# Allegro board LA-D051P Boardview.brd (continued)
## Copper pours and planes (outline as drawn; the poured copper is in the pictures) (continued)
VCCSA_B+ on TOP (solid shape): 147.25,118.74 147.25,117.91 147.19,117.85 145.73,117.85 145.47,118.1 145.47,119.18 145.66,119.37 146.61,119.37
VCCSA_B+ on BOTTOM (solid shape): 150.81,121.15 150.81,118.74 150.74,118.67 148.14,118.67 147.38,117.91 145.47,117.91 145.22,118.16 145.22,119.75 145.79,119.75 145.79,120.01 146.87,120.01 146.87,119.43 147.06,119.24 148.71,119.24 148.9,119.43 148.9,119.94 148.71,120.13 147,120.13 146.87,120.01 145.79,120.01 145.79,120.26 145.22,120.26 145.22,121.28 145.41,121.47 150.49,121.47
VDD_1.35V on BOTTOM (solid shape): 83.11,17.14 83.11,16.44 84,15.55 84.58,15.55 84.64,15.49 84.64,14.72 84.51,14.6 84.26,14.6 84.13,14.72 83.62,14.72 81.91,16.44 80.83,16.44 80.77,16.5 80.77,17.14 80.89,17.26 82.99,17.26
VDD_CHG on BOTTOM (solid shape): 45.4,18.91 45.4,17.71 45.27,17.58 45.27,16.37 45.59,16.06 45.59,14.98 45.52,14.91 45.46,14.91 45.4,14.98 45.4,15.93 44.63,16.69 44.63,18.85 44.76,18.98 45.33,18.98
VDDP_CHG on BOTTOM (solid shape): 46.28,18.91 46.28,17.64 46.16,17.52 45.97,17.52 45.78,17.33 45.78,16.37 46.03,16.12 46.03,14.98 45.97,14.91 45.84,14.91 45.78,14.98 45.78,16.06 45.46,16.37 45.46,17.52 45.65,17.71 45.65,18.91 45.71,18.98 46.22,18.98
VIN_1.8VALW on BOTTOM (solid shape): 87.94,25.9 87.94,24.95 86.92,23.93 86.92,23.68 85.15,21.9 84.83,21.9 84.83,22.47 83.43,22.47 83.43,21.9 83.11,21.9 82.99,22.03 82.99,22.6 85.72,25.33 85.72,25.9 85.97,26.15 87.69,26.15
+FAN_POWER on TOP (solid shape): 8.18,71.94 8.18,71.05 8.06,70.92 5.39,70.92 4.88,70.41 4.88,68.76 4.63,68.51 4.12,68.51 3.87,68.76 3.87,71.49 4.18,71.81 4.82,71.81 5.2,72.19 7.93,72.19
+FAN_POWER on BOTTOM (solid shape): 8.06,72.83 8.06,71.05 7.9,70.89 6.69,70.89 6.53,71.05 6.53,73.08 6.58,73.13 7.75,73.13
+GPU_CORE on TOP (solid shape): outline of 281 points within 60.57,70.91 70.35,79.3
+GPU_CORE on TOP (solid shape): outline of 548 points within 45.59,42.98 64.06,59.11
+GPU_CORE on BOTTOM (solid shape): 69.22,76.89 69.22,76.61 69.09,76.48 68.84,76.48 66.67,78.65 66.67,78.82 66.9,79.04 67.06,79.04
+GPU_CORE on BOTTOM (solid shape): 69.22,74.86 69.22,74.56 69.12,74.45 68.85,74.45 64.74,78.56 64.74,78.82 64.85,78.93 65.15,78.93
+GPU_CORE on BOTTOM (solid shape): 69.21,70.88 69.21,70.62 69.07,70.48 68.82,70.48 60.76,78.54 60.76,78.79 60.91,78.94 61.14,78.94
+GPU_CORE on BOTTOM (solid shape): 69.22,72.87 69.22,72.56 69.12,72.46 68.85,72.46 62.8,78.51 62.8,78.8 62.93,78.93 63.16,78.93
+GPU_CORE on BOTTOM (solid shape): 65.26,70.82 65.26,70.57 65.16,70.46 65.13,70.46 64.84,70.46 60.73,74.57 60.73,74.83 60.84,74.94 61.14,74.94
+GPU_CORE on BOTTOM (solid shape): 67.28,70.81 67.28,70.56 67.17,70.45 67.15,70.45 66.85,70.45 60.74,76.57 60.74,76.76 60.89,76.91 61.18,76.91
+GPU_CORE on BOTTOM (solid shape): 63.25,70.82 63.25,70.6 63.06,70.42 62.89,70.42 61.08,72.23 60.91,72.23 60.66,71.98 60.66,71.43 61.35,70.73 61.35,70.52 61.23,70.39 60.84,70.39 60.21,71.02 60.21,72.27 60.89,72.95 61.11,72.95
+GPU_CORE on BOTTOM (solid shape): 59.3,57.4 59.3,57.01 59.43,56.89 60.38,56.89 60.51,57.01 60.51,57.4 60.64,57.52 60.89,57.52 61.02,57.4 61.02,55.36 60.83,55.17 55.75,55.17 55.37,54.79 55.37,41.46 55.1,41.19 51.77,41.19 50.62,42.34 50.46,42.9 49.99,42.54 47.11,42.54 46.6,43.04 46.6,50.41 50.6,54.41 50.6,56.7 50.79,56.89 58.6,56.89 58.73,57.01 58.73,57.4 58.86,57.52 59.18,57.52
+GPU_CORE on IN1 (solid shape): outline of 2919 points within 46.98,42.98 71.24,78.57
+GPU_CORE on IN2 (solid shape): outline of 3563 points within 45.97,42.98 70.54,79.81
+GPU_CORE on IN3 (solid shape): outline of 3563 points within 45.97,42.98 70.54,79.81
+GPU_CORE on VCC: 49.88,43.62 46.86,46.64 46.86,57.99 53.5,64.63 55.98,64.63 60.13,68.78 60.13,78.75 60.68,79.3 68.98,79.3 69.72,78.56 69.72,64.82 69.14,64.25 68,64.25 67.05,63.3 67.05,60.61 65.98,59.54 61.51,59.54 60.7,58.73 60.7,57.71 61.14,57.27 61.14,54.71 56.7,50.26 56.7,44.86 55.45,43.62
+INV_PWR_SRC on TOP (solid shape): 5.51,79.32 7.02,79.32 7.49,78.85 7.49,74.2 7.32,74.04 5.52,74.04 5.11,74.45 5.11,75.64 4.63,76.12 4.63,77.72 4.34,78.01 1.87,78.01 1.76,78.12 1.76,79.33 1.86,79.43 5.39,79.43
+INV_PWR_SRC on BOTTOM: 3.19,80.24 3.2,80.24 5.79,80.24 6.1,79.93 6.1,78.85 6.19,78.76 11.06,78.76 11.33,78.48 11.33,75.3 13.47,73.16 13.47,71.82 14.57,70.72 14.57,64.65 14.52,64.6 12.41,64.6 12.22,64.79 12.22,70.17 9.71,72.69 9.71,76.41 9.24,76.88 4.41,76.88 3.26,78.03 1.34,78.03 1.12,78.25 1.12,80.17 1.2,80.24
+LAN_REGOUT on BOTTOM (solid shape): 173.28,111.75 173.28,106.48 173.92,105.85 173.92,104.88 173.91,104.85 173.87,104.83 173.21,104.83 173.09,104.95 173.09,105.53 173.06,105.57 172.4,106.23 172.4,107.5 171.76,108.13 171.76,111.88 172.01,112.13 172.9,112.13
+LAN_VDD10 on BOTTOM (solid shape): 171.51,113.15 171.51,108.89 171.38,108.77 170.24,108.77 169.86,109.15 169.86,113.02 170.11,113.28 171.38,113.28
+LAN_VDD10 on IN1 (solid shape): outline of 287 points within 169.86,101.27 180.14,113.24
+LAN_VDD33 on TOP (solid shape): 188.65,95.81 188.65,95.43 188.08,95.43 188.08,94.92 188.65,94.92 188.65,94.48 188.59,94.42 188.08,94.42 187.7,94.03 187.7,91.3 187.38,90.99 186.62,90.99 186.37,91.24 186.37,95.37 186.94,95.94 188.52,95.94
+LAN_VDD33 on TOP (solid shape): outline of 227 points within 169.79,99.95 180.21,107.88
+LAN_VDD33 on BOTTOM (solid shape): 171.44,103.69 171.44,102.92 171.13,102.61 171.13,102.23 171,102.1 169.98,102.1 169.79,102.29 169.79,103.62 169.92,103.75 171.38,103.75
+LAN_VDD33 on BOTTOM (solid shape): 190.3,95.9 190.3,92.01 189.28,90.99 186.94,90.99 186.55,91.38 186.55,92.22 186.87,92.54 188.46,92.54 189.01,93.09 189.01,95.84 189.2,96.02 190.18,96.02
+LAN_VDD33 on BOTTOM (solid shape): 178.08,106.3 178.08,105.69 178.03,105.64 177.63,105.64 177.48,105.5 177.47,105.49 177.26,105.38 177.12,105.19 177.1,105.17 177.07,105.16 176.94,105.16 176.87,105.24 176.87,106.02 177.07,106.23 177.12,106.23 177.27,106.38 178.01,106.38
+LAN_VDD33 on IN1 (solid shape): 177.8,100.89 177.8,100.04 177.72,99.97 177.15,99.97 177.15,99.97 176.14,99.97 175.88,100.23 175.88,100.97 175.94,101.04 177.65,101.04
+LAN_VDD33 on IN1 (solid shape): 187.8,92.87 187.8,91.25 187.47,90.92 186.87,90.92 186.4,91.39 186.4,92.82 187.03,93.45 187.22,93.45
+LAN_VDDREG on BOTTOM (solid shape): 172.93,105.52 172.93,104.93 172.96,104.91 172.96,104.89 173.02,104.8 173.11,104.74 173.12,104.74 173.16,104.7 174,104.7 174.03,104.69 174.05,104.65 174.05,104.5 174.03,104.46 174,104.45 172.9,104.45 172.78,104.58 172.4,104.58 172.33,104.51 170.3,104.51 170.17,104.64 170.17,105.97 170.36,106.16 172.28,106.16
+LCDVDD on TOP (solid shape): 11.59,86.23 11.59,83.46 11.29,83.17 10.45,83.17 10.12,83.5 10.12,86.32 10.21,86.41 11.4,86.41
+LCDVDD on TOP (solid shape): 21.73,74.56 21.73,73.5 21.36,73.14 19.74,73.14 19.57,73.3 19.57,74.65 19.89,74.96 21.32,74.96
+LCDVDD on IN3 (solid shape): 13.2,84.15 13.2,83.16 13.01,82.96 10.48,82.96 10.2,83.25 10.2,84.2 10.47,84.47 12.88,84.47
+LCDVDD on IN3 (solid shape): 21.15,74.62 21.15,73.96 20.6,73.41 19.97,73.41 18.59,74.79 18.59,75.02 19.47,75.91 19.87,75.91
+LCDVDD_CONN on TOP (solid shape): 9.42,88.89 9.42,84.95 9.76,84.61 9.76,83.86 9.71,83.81 8.57,83.81 8.41,83.97 8.41,84.74 7.42,85.73 7.42,87.24 7.36,87.3 3.8,87.3 3.61,87.49 3.61,88.57 3.8,88.76 5.58,88.76 5.89,89.08 9.23,89.08
+LCDVDD_CONN on BOTTOM (solid shape): 5.64,88.83 5.64,87.56 5.52,87.43 4.63,87.43 4.24,87.04 4.02,86.97 3.88,86.8 1.71,86.8 1.58,86.92 1.58,87.63 1.68,87.74 2.38,87.74 3.01,88.37 3.78,88.37 3.81,88.39 3.84,88.39 4.35,88.9 5.57,88.9
+V_TS on TOP (solid shape): 11.87,100.58 11.87,100.13 12.12,99.88 14.73,99.88 15.68,98.92 15.68,94.92 15.55,94.8 13.9,94.8 13.71,94.99 13.71,97.59 12.82,98.48 10.72,98.48 10.6,98.6 10.6,99.56 10.41,99.75 9.33,99.75 9.14,99.94 9.14,100.51 9.26,100.64 11.8,100.64
+VDISPLAY_VCC on TOP (solid shape): 203,81.21 203,79.68 202.74,79.42 201.09,79.42 200.47,78.8 197.85,78.8 197.73,78.92 197.73,80.83 198.11,81.21 199.32,81.21 199.45,81.33 200.59,81.33 200.84,81.59 202.62,81.59
AUD_HP_OUT_R_CN on TOP (solid shape): 197.82,28.05 199.22,28.05 199.32,27.94 199.32,27.03 199.14,26.85 198.57,26.85 198.31,27.11 197.51,27.11 197.13,27.49 197.13,28.01 197.34,28.22 197.64,28.22
BS_+1VALWP on BOTTOM (solid shape): 181.48,52.89 181.48,52 181.41,51.93 180.78,51.93 180.59,51.74 180.59,51.17 180.46,51.05 179.63,51.05 179.57,51.11 179.57,51.74 180.78,52.95 181.41,52.95
BST1_VGA on BOTTOM (solid shape): 74.03,47.3 74.03,45.65 74.86,44.82 74.86,44.06 74.8,44 74.61,44 73.15,45.46 73.15,47.36 73.27,47.49 73.84,47.49
BST1_VGA_R on BOTTOM (solid shape): 71.68,46.6 72.51,46.6 72.57,46.54 72.57,45.71 72.51,45.65 70.54,45.65 70.48,45.71 70.48,47.17 70.61,47.3 70.99,47.3
BST2_VGA on BOTTOM (solid shape): 74.86,41.71 74.86,40.95 74.8,40.89 74.35,40.89 73.72,40.25 73.72,39.36 73.46,39.11 73.46,38.54 73.34,38.41 73.02,38.41 72.89,38.54 72.89,40.44 74.03,41.58 74.48,41.58 74.67,41.77 74.8,41.77
BST2_VGA_R on BOTTOM (solid shape): 72.32,40.19 72.32,38.54 72.13,38.35 71.81,38.35 71.62,38.54 71.62,39.17 71.49,39.3 70.35,39.3 70.29,39.36 70.29,40.19 70.35,40.25 72.26,40.25
BST_1.35V on BOTTOM (solid shape): 88.77,13.64 88.77,12.88 88.7,12.82 88.07,12.82 87.5,13.39 86.42,13.39 86.35,13.45 86.35,13.58 86.42,13.64 87.37,13.64 87.43,13.71 88.7,13.71
BST_1.35V_R on BOTTOM (solid shape): 90.1,15.36 90.1,13.63 90.82,12.91 90.82,11.98 90.71,11.87 90.36,11.87 89.46,12.76 89.46,15.36 89.53,15.42 90.04,15.42
BST_3V on BOTTOM (solid shape): 63.05,14.09 63.05,13.26 63.24,13.07 63.24,10.53 63.11,10.41 62.22,10.41 62.16,10.47 62.16,11.17 62.79,11.8 62.79,14.09 62.86,14.15 62.99,14.15
BST_5V on BOTTOM (solid shape): 64.13,25.65 64.13,22.22 64.06,22.15 63.24,22.15 63.11,22.28 63.11,23.11 63.68,23.68 63.68,25.84 63.75,25.9 63.87,25.9
CORE_SNUB on TOP (solid shape): 109.72,116.13 109.72,114.48 109.66,114.42 107.82,114.42 107.56,114.67 107.56,115.88 107.88,116.2 109.66,116.2
CORE_SW on TOP (solid shape): 113.02,116.13 113.02,114.55 112.9,114.42 111.31,114.42 111.25,114.48 111.25,116.13 111.37,116.26 112.9,116.26
CORE_SW on BOTTOM (solid shape): 115.56,116.83 115.56,115.5 115.44,115.37 115.06,115.37 114.86,115.18 114.86,115.12 115.12,114.86 115.37,114.86 115.56,114.67 115.56,113.34 115.44,113.21 109.34,113.21 108.39,114.16 106.29,114.16 106.23,114.23 106.23,116.2 109.66,116.2 110.55,117.09 115.31,117.09
CPU_B+ on TOP (solid shape): 103.5,118.86 103.5,115.94 103.88,115.56 103.88,114.23 103.69,114.04 102.48,114.04 100.58,115.94 100.58,118.86 100.7,118.99 103.37,118.99
CPU_B+ on BOTTOM (solid shape): 50.6,118.74 50.6,115.56 50.16,115.12 46.67,115.12 46.41,115.37 46.41,118.93 46.6,119.12 50.22,119.12
CPU_B+ on BOTTOM (solid shape): 145.03,120.58 145.03,118.74 144.77,118.48 143.19,118.48 142.87,118.8 142.87,119.63 143.95,120.7 144.9,120.7
CPU_B+ on BOTTOM (solid shape): 103.5,118.93 103.5,117.4 104.01,116.89 104.01,113.85 103.63,113.85 103.5,113.72 103.5,113.21 103.37,113.08 103.24,113.08 103.18,113.15 103.18,113.72 103.05,113.85 102.48,113.85 102.48,116.39 101.78,117.09 100.83,117.09 100.58,117.34 100.58,118.93 100.7,119.05 103.37,119.05
CPU_B+ on BOTTOM (solid shape): outline of 87 points within 71.49,104.13 80.77,119.88
CPU_B+ on IN1 (solid shape): 56.83,117.85 56.83,116.45 55.75,115.37 49.59,115.37 48.89,116.07 48.89,118.61 49.52,119.24 55.43,119.24
CPU_B+ on IN1 (solid shape): 76.83,120.13 75.11,118.42 70.22,118.42 70.22,120.64 70.54,120.96 76.83,120.96
CPU_B+ on IN1 (solid shape): 104.39,120.58 104.39,119.12 103.56,119.12 102.8,118.36 102.8,117.28 102.48,116.96 101.21,116.96 100.96,117.21 100.96,118.67 100.07,119.56 100.07,119.88 100.83,120.64 104.32,120.64
CPU_B+ on IN1 (solid shape): 143.98,120.18 143.98,120.18 144.47,119.69 144.47,118.69 144.14,118.36 144.14,118.36 143.69,117.91 141.53,117.91 141.34,118.1 141.34,119.43 142.72,119.43 143.52,120.23 143.93,120.23
DRMOS on BOTTOM (solid shape): 102.29,114.55 102.29,114.42 102.23,114.35 101.85,114.35 101.02,113.53 100.26,113.53 100.2,113.59 100.2,114.16 100.32,114.29 101.15,114.29 101.47,114.61 102.23,114.61
GPU_B+ on TOP (solid shape): 83.62,105.02 83.56,104.96 83.56,103.31 83.43,103.18 82.23,103.18 82.1,103.31 82.1,104.89 82.99,105.78 82.99,106.42 83.11,106.54 83.62,106.54
GPU_B+ on BOTTOM (solid shape): 83.62,107.31 83.62,103.12 83.81,102.92 83.81,99.75 83.43,99.75 83.31,99.62 83.31,98.8 83.56,98.54 83.56,97.59 83.5,97.53 82.99,97.53 82.92,97.59 82.92,98.16 82.99,98.23 82.99,99.62 82.86,99.75 82.29,99.75 82.29,102.67 81.02,103.94 81.02,107.37 81.21,107.56 83.37,107.56
GPU_B+ on IN1 (solid shape): 83.62,104.7 83.62,100.19 83.18,99.75 81.91,99.75 81.59,100.07 81.59,104.58 82.04,105.02 83.31,105.02
GPU_PLLVDD on TOP (solid shape): 72.57,76.73 72.57,73.87 73.1,73.34 73.1,72.49 73.03,72.41 72.01,72.41 71.81,72.61 71.81,76.72 71.87,76.78 72.52,76.78
GT_SNUB1 on TOP (solid shape): 94.81,104.32 94.81,101.64 94.63,101.46 93.47,101.46 93.02,101.91 93.02,104.32 93.08,104.39 94.75,104.39
GT_SW1 on TOP (solid shape): 91.99,101.49 90.6,101.49 90.34,101.74 90.34,102.65 90.84,103.14 91.99,103.14
GT_SW1 on BOTTOM (solid shape): 90.89,102.89 90.89,101.68 90.61,101.4 89.66,101.4 89.46,101.21 89.46,101.08 89.66,100.89 90.16,100.89 90.29,100.77 90.29,99.37 90.1,99.18 87.81,99.18 86.92,100.07 86.16,100.07 86.1,100.13 86.1,102.67 86.42,102.99 90.79,102.99
INT-SPK-L+ on TOP (solid shape): 202.04,20.71 202.04,20.2 202.04,20.19 202.04,19.94 202.55,19.44 203.76,19.44 203.92,19.28 203.92,18.5 203.74,18.32 202.04,18.32 200.97,19.38 200.97,20.3 200.95,20.33 200.95,20.91 201.1,21.06 201.68,21.06
INT-SPK-L+ on BOTTOM (solid shape): 201.73,20.6 201.73,19.94 201.33,19.54 199.17,19.54 199.12,19.59 199.12,19.74 199.17,19.79 200.72,19.79 201.12,20.2 201.12,20.55 201.28,20.71 201.63,20.71
INT-SPK-L- on TOP (solid shape): 206.05,20.07 206.05,18.57 205.89,18.41 204.97,18.41 204.83,18.55 204.83,19.44 204.35,19.92 202.49,19.92 202.16,20.25 202.16,20.83 202.42,21.09 205.03,21.09
INT-SPK-L- on BOTTOM (solid shape): 203.87,20.76 203.87,20.3 203.66,20.1 202.9,20.1 201.94,19.13 201.48,19.13 201.43,19.18 199.17,19.18 199.12,19.23 199.12,19.36 199.14,19.38 201.38,19.38 202.11,20.12 202.11,20.4 202.53,20.81 203.81,20.81
INT-SPK-R+ on TOP (solid shape): 209.1,19.31 209.1,18.52 208.9,18.32 206.43,18.32 206.23,18.52 206.23,19.21 206.48,19.46 208.95,19.46
INT-SPK-R+ on BOTTOM (solid shape): 201.28,18.17 201.28,17.5 201.22,17.45 200.95,17.45 200.59,17.81 200.59,18.19 200.41,18.37 199.19,18.37 199.12,18.44 199.12,18.55 199.17,18.6 200.84,18.6
INT-SPK-R+ on IN3 (solid shape): 207.93,19.54 207.93,18.78 207.72,18.57 201.6,18.57 201.28,18.24 201.28,17.51 201.22,17.45 200.58,17.45 200.39,17.64 200.39,19.13 200.67,19.41 201.36,19.41 201.71,19.76 207.71,19.76
INT-SPK-R- on TOP (solid shape): 212.88,19.44 212.88,18.77 212.48,18.37 210.11,18.37 209.91,18.57 209.91,19.38 210.11,19.59 212.73,19.59
INT-SPK-R- on BOTTOM (solid shape): 202.44,18.01 202.44,16.95 202.29,16.79 201.99,16.79 201.81,16.97 201.81,17.89 200.92,18.77 199.17,18.77 199.12,18.83 199.12,18.95 199.17,19 201.1,19 201.15,19.05 201.4,19.05
INT-SPK-R- on IN3 (solid shape): 213.06,19.36 213.06,18.83 212.78,18.55 211.51,18.55 209.78,16.82 202.65,16.82 202.56,16.74 201.9,16.74 201.85,16.79 201.85,17.76 202.05,17.95 209.55,17.95 211.24,19.64 212.78,19.64
KB_BL_PWM on TOP (solid shape): 124.83,24.38 124.83,23.05 124.72,22.94 121.08,22.94 120.91,23.11 120.91,24.38 121.05,24.52 124.69,24.52
LG1_VGA on BOTTOM (solid shape): 62.03,47.49 62.41,47.49 62.6,47.3 62.6,46.79 62.41,46.6 61.33,46.6 61.21,46.73 61.21,47.62 61.33,47.74 61.78,47.74
LG1_VGA on BOTTOM (solid shape): 73.53,43.43 74.42,43.43 74.48,43.36 74.48,43.23 74.42,43.17 72.38,43.17 72.26,43.3 72.26,43.55 72.38,43.68 73.27,43.68
LG1_VGA on IN3 (solid shape): 62.79,47.43 62.79,47.24 62.16,46.6 61.33,46.6 61.21,46.73 61.21,47.68 61.4,47.87 62.35,47.87
LG1_VGA on IN3 (solid shape): 71.43,44.31 71.88,44.31 72.45,43.74 73.21,43.74 73.4,43.55 73.4,43.23 73.27,43.11 71.94,43.11 71.62,43.43 70.92,43.43 70.22,44.12 70.22,44.19 70.8,44.76 70.99,44.76
LG2_VGA on BOTTOM (solid shape): 66.6,44.76 66.6,43.87 66.48,43.74 65.53,43.74 65.33,43.93 65.33,44.76 65.46,44.89 66.48,44.89
LG2_VGA on BOTTOM (solid shape): 74.48,42.54 74.48,42.41 74.42,42.35 73.46,42.35 72.95,41.84 72.13,41.84 72,41.96 72,42.35 72.13,42.47 73.21,42.47 73.34,42.6 74.42,42.6
LG2_VGA on IN3 (solid shape): 67.75,44.57 67.75,44 67.49,43.74 66.22,43.74 66.1,43.87 66.1,44.76 66.22,44.89 67.43,44.89
LG2_VGA on IN3 (solid shape): 71.75,42.41 72.95,42.41 73.15,42.22 73.15,41.96 73.02,41.84 70.61,41.84 70.61,42.66 70.8,42.85 71.3,42.85
LG_1.35V on BOTTOM (solid shape): 87.5,20.76 87.5,19.93 87.37,19.8 86.92,19.8 86.42,20.31 86.42,20.69 86.61,20.88 87.37,20.88
LG_1.35V on BOTTOM (solid shape): 86.92,16.06 86.92,15.29 86.29,14.66 86.04,14.66 85.97,14.72 85.97,15.49 86.04,15.55 86.16,15.55 86.42,15.8 86.42,16.06 86.54,16.18 86.8,16.18
LG_1.35V on IN3 (solid shape): 87.75,20.63 87.75,19.8 87.56,19.61 87.18,19.61 86.42,20.37 86.42,20.69 86.61,20.88 87.5,20.88
LG_1.35V on IN3 (solid shape): 87.75,15.99 86.86,15.1 86.54,15.1 86.42,15.23 86.42,16.12 86.54,16.25 86.73,16.25 86.99,16.5 86.99,17.01 87.12,17.14 87.75,17.14
LGATE_CHG on BOTTOM (solid shape): 44.13,23.87 44.13,22.83 44.05,22.75 43.08,22.75 42.41,23.42 42.41,23.93 42.54,24.06 43.94,24.06
LGATE_CHG on BOTTOM (solid shape): 46.41,17.2 46.41,14.98 46.35,14.91 46.22,14.91 46.16,14.98 46.16,16.25 45.9,16.5 45.9,17.2 46.03,17.33 46.28,17.33
LGATE_CHG on IN3 (solid shape): 43.49,23.93 43.49,22.22 43.43,22.15 42.6,22.15 42.47,22.28 42.47,23.93 42.6,24.06 43.36,24.06
LGATE_CHG on IN3 (solid shape): 46.35,18.22 46.35,16.31 46.28,16.25 45.78,16.25 45.65,16.37 45.65,17.52 45.27,17.9 45.27,18.47 45.46,18.66 45.9,18.66
LX1_VGA on TOP (solid shape): 59.11,50.35 59.11,47.93 58.86,47.68 58.48,47.68 58.29,47.87 58.29,48.44 58.1,48.63 57.59,48.63 57.46,48.76 57.46,50.28 57.59,50.41 59.05,50.41
LX1_VGA on BOTTOM (solid shape): 74.48,43.74 74.48,43.62 74.42,43.55 73.59,43.55 72.95,44.19 70.61,44.19 70.48,44.31 70.48,45.01 70.54,45.08 73.15,45.08
LX1_VGA on BOTTOM (solid shape): 60.38,53.46 60.38,51.36 61.14,50.6 66.16,50.6 66.29,50.47 66.29,48 66.16,47.87 62.16,47.87 61.91,48.12 57.78,48.12 57.4,48.51 57.4,53.52 57.78,53.9 59.94,53.9
LX1_VGA on IN3 (solid shape): 59.05,49.9 59.05,49.14 58.73,48.82 57.59,48.82 57.46,48.95 57.46,49.9 57.65,50.09 58.86,50.09
LX1_VGA on IN3 (solid shape): 73.4,44.89 73.4,44.57 73.27,44.44 72.45,44.44 71.56,45.33 71.56,45.97 71.62,46.03 72.26,46.03
LX2_VGA on TOP (solid shape): 59.11,44.06 59.11,41.52 58.92,41.33 58.54,41.33 58.35,41.52 58.35,42.22 58.22,42.35 57.46,42.35 57.36,42.45 57.36,44.01 57.47,44.12 59.05,44.12
LX2_VGA on BOTTOM (solid shape): 60.89,46.09 60.89,44 61.4,43.49 65.78,43.49 65.84,43.43 65.84,40.82 65.78,40.76 57.65,40.76 57.27,41.14 57.27,46.16 57.52,46.41 60.57,46.41
LX2_VGA on BOTTOM (solid shape): 74.48,42.16 74.48,41.84 74.35,41.71 73.97,41.71 73.21,40.95 70.35,40.95 70.29,41.01 70.29,41.58 70.35,41.65 73.02,41.65 73.59,42.22 74.42,42.22
LX2_VGA on IN3 (solid shape): 59.18,43.43 59.18,43.11 58.73,42.66 57.59,42.66 57.46,42.79 57.46,43.74 57.59,43.87 58.73,43.87
LX2_VGA on IN3 (solid shape): 73.15,41.27 73.15,41.08 72.51,40.44 70.03,40.44 69.84,40.63 69.84,41.27 70.03,41.46 72.95,41.46
LX_1.8VALW on BOTTOM (solid shape): 89.59,31.55 89.59,30.73 89.53,30.66 87.31,30.66 87.12,30.47 87.12,27.74 86.54,27.17 85.65,27.17 85.46,27.36 85.46,30.92 86.23,31.68 89.46,31.68
LX_1.35V on BOTTOM (solid shape): 88.7,17.71 88.83,17.58 94.67,17.58 94.99,17.26 94.99,13.58 94.74,13.33 91.56,13.33 91.12,13.77 91.12,15.49 90.73,15.87 88.96,15.87 88.77,15.68 88.77,14.53 88.7,14.47 87.5,14.47 87.24,14.22 86.48,14.22 86.42,14.28 86.42,14.47 86.54,14.6 86.73,14.6 87.69,15.55 87.69,15.98 91.32,15.98 91.32,15.93 91.34,15.87 91.36,15.82 91.39,15.78 91.42,15.74 91.46,15.7 91.51,15.67 91.55,15.65 91.61,15.63 91.66,15.62 91.71,15.62 91.77,15.63 91.82,15.65 91.87,15.67 91.91,15.7 91.95,15.74 91.99,15.78 92.02,15.82 92.04,15.87 92.05,15.93 92.06,15.98 92.06,16.03 92.05,16.09 92.03,16.14 92,16.19 91.97,16.23 91.93,16.27 91.89,16.3 91.84,16.33 91.79,16.35 91.74,16.36 91.69,16.36 91.63,16.36 91.58,16.35 91.53,16.33 91.48,16.3 91.44,16.27 91.4,16.23 91.37,16.19 91.35,16.14 91.33,16.09 91.32,16.03 91.32,15.98 87.69,15.98 87.69,20.31 88.7,20.31
LX_3V on BOTTOM (solid shape): 60.89,14.41 60.89,14.28 60.76,14.15 60.76,13.71 60.64,13.58 59.75,13.58 59.62,13.71 59.62,14.02 60.06,14.47 60.83,14.47
LX_3V on BOTTOM (solid shape): 67.68,17.2 67.68,10.15 67.43,9.9 65.21,9.9 64.7,10.41 63.43,10.41 63.37,10.47 63.37,14.02 63.11,14.28 63.11,14.91 63.18,14.98 64.06,14.98 64.07,14.98 65.84,14.98 66.35,15.49 66.35,17.2 66.41,17.26 67.62,17.26
LX_3V on IN3 (solid shape): 64.57,13.96 64.57,13.2 64.38,13.01 59.81,13.01 59.62,13.2 59.62,13.96 59.75,14.09 64.45,14.09
LX_5V on BOTTOM (solid shape): 61.78,26.15 61.78,25.96 61.59,25.77 61.59,25.45 61.46,25.33 60.57,25.33 60.45,25.45 60.45,26.03 60.64,26.22 61.72,26.22
LX_5V on BOTTOM (solid shape): 68.13,29.46 68.13,26.93 68.57,26.48 68.57,21.47 68.48,21.38 66.06,21.38 65.28,22.15 64.38,22.15 64.32,22.22 64.32,25.71 64,26.03 64,26.66 64.06,26.72 66.6,26.72 66.92,27.04 66.92,29.46 66.99,29.52 68.07,29.52
LX_5V on IN3 (solid shape): 66.16,26.6 66.16,26.34 64.7,24.88 60.64,24.88 60.45,25.07 60.45,25.71 60.57,25.84 64.19,25.84 65.08,26.72 66.03,26.72
MIC_IN_R on BOTTOM (solid shape): 197.07,33.9 197.36,33.75 197.66,33.9 198.45,33.9 198.65,33.71 198.65,33.31 198.42,33.08 196.65,33.08 196.59,33.01 196.21,33.01 195.76,32.57 191.83,32.57 191.83,33.46 193.92,33.46 194.37,33.9
MIC_IN_R on IN3 (solid shape): 198.56,34.21 199.42,34.21 199.66,33.96 199.66,32.81 199.48,32.63 197.61,32.63 197.16,33.07 197.16,33.81 197.58,33.82 197.7,34.22 198.56,34.22
Net_27 on IN1: 99.87,19.09 101.14,19.09
Net_28 on IN1: 162.12,3.27 163.39,3.27
Net_28 on IN1: 168.47,3.27 169.74,3.27
Net_28 on IN1: 100.25,12.74 101.52,12.74
Net_29 on IN1: 63.81,10.79 65.08,10.79
Net_30 on IN1: 70.16,10.79 71.43,10.79
Net_31 on IN1: 69.18,27.68 70.45,27.68
Net_32 on IN1: 72.12,21.92 73.39,21.92
Net_33 on IN1: 65,22.56 66.27,22.56
Net_34 on IN1: 86.95,54.25 88.22,54.25
Net_35 on IN1: 87.2,47.9 88.47,47.9
Net_36 on IN1: 79.62,48.47 80.89,48.47
Net_37 on IN1: 77.91,54.88 79.18,54.88
Net_38 on IN1: 44.71,116.49 45.98,116.49
Net_39 on IN1: 38.36,116.49 39.63,116.49
Net_40 on IN1: 19.89,117.01 21.16,117.01
Net_41 on IN1: 13.54,117.01 14.81,117.01
Net_42 on IN1: 13.98,107.98 15.25,107.98
Net_43 on IN1: 7.91,77.45 9.18,77.45
Net_44 on IN1: 3.19,50.3 4.46,50.3
Net_45 on IN1: 32.47,23.41 33.74,23.41
Net_46 on IN1: 38.82,23.41 40.09,23.41
Net_47 on IN1: 36.53,29.51 37.8,29.51
Net_48 on IN1: 44.34,36.44 45.61,36.44
Net_49 on IN1: 37.99,38.47 39.26,38.47
Net_216 on TOP (solid shape): 43.81,51.87 35.81,51.87 35.81,59.87 43.81,59.87
Net_217 on TOP (solid shape): 62.87,32.75 54.87,32.75 54.87,40.75 62.87,40.75
Net_218 on TOP (solid shape): 53.09,31.06 38.09,31.06 38.09,41.06 53.09,41.06
PEX_PLLVDD_GPU on TOP (solid shape): 64.96,69.59 64.95,69.59 64.95,68.18 65.19,67.94 65.55,67.94 65.64,67.85 65.64,67.25 65.56,67.17 63.31,67.17 63.22,67.26 63.22,68.49 63.41,68.49 63.41,68.43 63.42,68.38 63.44,68.33 63.46,68.28 63.49,68.24 63.53,68.2 63.57,68.17 63.61,68.14 63.66,68.12 63.72,68.11 63.77,68.1 63.82,68.11 63.87,68.12 63.92,68.14 63.97,68.17 64.01,68.2 64.05,68.24 64.08,68.28 64.1,68.33 64.12,68.38 64.13,68.43 64.13,68.49 64.12,68.54 64.1,68.59 64.08,68.64 64.05,68.68 64.01,68.72 63.97,68.76 63.92,68.78 63.87,68.8 63.82,68.81 63.77,68.82 63.72,68.81 63.66,68.8 63.61,68.78 63.57,68.76 63.53,68.72 63.49,68.68 63.46,68.64 63.44,68.59 63.42,68.54 63.41,68.49 63.22,68.49 63.22,69.52 63.43,69.72 64.83,69.72
PHASE_CHG on BOTTOM (solid shape): 47.75,18.41 47.75,17.58 47.05,16.88 47.05,16.44 46.86,16.25 46.86,15.87 46.79,15.8 46.79,14.98 46.73,14.91 46.6,14.91 46.54,14.98 46.54,18.28 46.73,18.47 47.68,18.47
PHASE_CHG on BOTTOM (solid shape): 44,29.39 44,27.49 44.44,27.04 45.97,27.04 46.22,26.79 46.22,24.57 46.02,24.36 39.41,24.36 39.17,24.12 39.17,21.39 38.16,21.39 38.09,21.45 38.09,28.63 38.35,28.88 40.09,28.88 40.73,29.52 43.87,29.52
PHASE_CHG on IN3 (solid shape): 44.51,25.71 44.51,25.58 44.32,25.39 42.6,25.39 42.47,25.52 42.47,26.41 42.6,26.53 43.68,26.53
PHASE_CHG on IN3 (solid shape): 47.43,20.06 47.43,17.33 47.05,16.95 47.05,16.37 46.92,16.25 46.6,16.25 46.54,16.31 46.54,19.55 46.41,19.68 46.41,20.5 46.98,20.5
PSID on TOP (solid shape): 23.49,111.62 23.49,110.74 23.3,110.54 22.47,110.54 22.22,110.8 22.22,111.37 21.77,111.81 20.5,111.81 20.25,112.07 20.25,112.51 20.44,112.7 22.41,112.7
RING2 on BOTTOM (solid shape): 191.57,31.87 191.57,31.66 191.56,31.55 191.57,31.44 191.57,31.23 191.32,30.98 191,30.98 190.68,30.66 190.68,30.22 190.56,30.09 190.11,30.09 190.01,30.19 190.01,30.2 189.94,30.3 189.84,30.37 189.83,30.37 189.67,30.53 189.67,31.3 189.73,31.36 190.05,31.36 190.62,31.93 191.51,31.93
RING2 on IN3 (solid shape): 191,30.98 191,29.33 190.87,29.2 190.18,29.2 190.09,29.29 190.08,29.31 190.05,29.42 189.99,29.51 189.99,29.87 189.99,29.88 190.02,30.03 189.99,30.18 189.99,30.19 189.99,31.04 190.11,31.17 190.81,31.17
RING2 on IN3 (solid shape): 192.72,18.28 192.72,18.07 192.68,17.99 192.27,17.92 192.13,17.63 192.13,17.58 190.87,17.58 190.49,17.96 190.49,18.15 190.62,18.28 191.93,18.28 192.16,18.51 192.49,18.51
RING2_R on BOTTOM (solid shape): 196.34,31.74 197.41,31.74 197.54,31.61 197.54,31.04 197.16,30.66 196.9,30.66 196.58,30.78 196.26,30.66 195.07,30.66 194.62,31.1 194.55,31.2 194.43,31.3 194.4,31.3 194.3,31.34 194.19,31.35 193.48,31.35 193.36,31.34 193.26,31.3 192.84,31.3 192.72,31.17 191.83,31.17 191.83,31.97 191.83,32.06 191.89,32.12 195.95,32.12
RING2_R on IN3 (solid shape): 197.74,32.11 197.74,31.12 197.67,31.04 196.4,31.04 196.07,31.37 196.07,32.85 196.14,32.92 196.93,32.92
RING2_R on IN3 (solid shape): 210.39,37.39 210.39,36.73 210.27,36.61 208.69,36.61 208.69,36.63 208.11,37.22 208.11,37.22 207.98,37.34 206.75,37.34 206.55,37.48 206.3,37.53 205.39,37.53 205.14,37.48 204.94,37.34 202.65,37.34 202.45,37.48 202.2,37.53 201.29,37.53 201.04,37.48 200.84,37.34 199.55,37.34 199.35,37.55 199.35,37.93 199.57,38.15 209.63,38.15
SA_SNUB on TOP (solid shape): 152.08,117.28 151.06,117.28 151,117.34 151,117.91 150.68,118.23 149.73,118.23 149.66,118.29 149.66,118.86 149.73,118.93 152.08,118.93
SA_SW on TOP (solid shape): 154.87,118.8 154.87,114.74 153.41,113.28 148.71,113.28 148.46,113.53 148.46,114.16 148.52,114.23 152.46,114.23 153.66,115.43 153.66,118.86 153.73,118.93 154.74,118.93
SA_SW on BOTTOM (solid shape): 155.63,119.05 155.63,118.16 155.44,117.97 155.12,117.97 155,117.85 155,117.59 155.12,117.47 155.44,117.47 155.63,117.28 155.63,116.01 155.31,115.69 153.22,115.69 152.77,116.13 152.77,117.09 152.52,117.34 148.2,117.34 148.2,118.42 151.63,118.42 152.39,119.18 155.5,119.18
SLEEVE on BOTTOM (solid shape): 190.94,33.46 191.51,33.46 191.57,33.39 191.57,33.19 191.56,33.07 191.57,32.96 191.57,32.69 191.45,32.57 190.75,32.57 190.05,31.87 189.79,31.87 189.67,32 189.67,32.82 189.48,33.01 189.48,33.58 189.54,33.65 190.75,33.65
SLEEVE on IN3 (solid shape): 191.38,32.76 191.38,31.93 191.13,31.68 189.86,31.68 189.6,31.93 189.6,32.69 189.86,32.95 191.19,32.95
SLEEVE on IN3 (solid shape): 193.73,19.55 193.73,19.23 193.22,18.72 192.63,18.72 192.59,18.76 192.06,18.76 191.83,18.53 191.64,18.53 191.64,19.29 192.02,19.67 192.46,19.67 192.46,19.68 193.6,19.68
SNB_+1VALWP on BOTTOM (solid shape): 175.16,46.71 175.16,45 175.09,44.93 172.48,44.93 172.33,45.08 172.33,46.79 172.54,47 174.87,47
SNUB_1.8VALW on BOTTOM (solid shape): 88.32,29.9 88.32,28.76 88,28.44 87.37,28.44 87.31,28.5 87.31,29.9 87.37,29.96 88.26,29.96
SNUB_VGA1 on TOP (solid shape): 62.79,50.09 62.79,48.82 62.54,48.57 60.76,48.57 60.64,48.7 60.64,50.22 60.83,50.41 62.48,50.41
SNUB_VGA2 on TOP (solid shape): 62.73,43.81 62.73,42.47 62.6,42.35 60.76,42.35 60.7,42.41 60.7,44 60.76,44.06 62.48,44.06
SPK_L1-_CONN on TOP (solid shape): 205.99,18.09 205.99,15.69 206.23,15.45 206.23,14.43 206.15,14.36 205.01,14.36 204.88,14.48 204.88,18.13 204.94,18.18 205.89,18.18
SPK_L1-_CONN on BOTTOM (solid shape): 206.18,19.36 206.18,15.68 206.56,15.29 206.56,13.26 206.3,13.01 205.92,13.01 205.67,13.26 205.67,14.91 205.03,15.55 205.03,18.22 204.78,18.47 204.78,19.61 205.03,19.87 205.67,19.87
SPK_L2+_CONN on TOP (solid shape): 203.97,18.08 203.97,15.24 204.36,14.85 204.36,13.97 204.27,13.88 203.02,13.88 202.86,14.04 202.86,18.08 203,18.22 203.83,18.22
SPK_L2+_CONN on BOTTOM (solid shape): 204.02,19.49 204.02,18.47 203.76,18.22 203.76,17.2 203.76,17.17 203.76,16.67 203.76,16.65 203.76,15.68 204.4,15.04 205.03,15.04 205.29,14.79 205.29,13.26 205.03,13.01 204.65,13.01 202.73,14.94 202.74,14.97 202.79,15.32 202.62,15.63 202.62,19.23 203.26,19.87 203.64,19.87
SPK_R1-_CONN on TOP (solid shape): 211.08,18.08 211.08,15.73 211.33,15.47 211.33,14.08 211,13.75 210.52,13.75 209.96,14.3 209.96,18.13 210.05,18.22 210.94,18.22
SPK_R1-_CONN on BOTTOM (solid shape): 211,19.61 211,18.72 211.38,18.34 211.38,14.66 209.73,13.01 208.34,13.01 208.21,13.14 208.21,14.66 208.46,14.91 209.73,14.91 210.37,15.55 210.37,17.45 209.73,18.09 209.73,19.36 210.11,19.74 210.88,19.74
SPK_R2+_CONN on TOP (solid shape): 209,18.12 209,14.5 208.91,14.41 207.45,14.41 207.22,14.63 207.22,15.65 207.63,16.06 207.63,16.97 207.63,18.01 207.83,18.22 208.91,18.22
SPK_R2+_CONN on BOTTOM (solid shape): 209.1,19.49 209.1,17.96 208.72,17.58 208.72,15.68 207.83,14.79 207.83,13.39 207.45,13.01 207.19,13.01 206.94,13.26 206.94,15.29 207.57,15.93 207.57,17.96 207.96,18.34 207.96,19.49 208.21,19.74 208.84,19.74
SW_+1VALWP on BOTTOM (solid shape): 178.87,48.12 180.4,46.6 180.4,44.7 180.14,44.44 177.48,44.44 175.32,42.28 173.48,42.28 173.41,42.35 173.41,43.43 173.48,43.49 174.87,43.49 176.52,45.14 176.52,46.85 177.73,48.06 177.73,49.46 178.87,49.46
UG2_VGA on BOTTOM (solid shape): 66.73,39.17 66.73,38.41 66.54,38.22 65.53,38.22 65.33,38.41 65.33,39.04 65.65,39.36 66.54,39.36
UG2_VGA on BOTTOM (solid shape): 75.24,41.71 75.24,40.44 74.73,39.93 74.29,39.93 74.16,40.06 74.16,40.31 74.54,40.69 74.8,40.69 74.99,40.89 74.99,41.71 75.05,41.77 75.18,41.77
UG2_VGA on IN3 (solid shape): 75.18,40.57 75.18,40.12 73.78,38.73 72.89,38.73 72.89,39.68 72.95,39.74 73.46,39.74 74.54,40.82 74.92,40.82
UG2_VGA on IN3 (solid shape): 68.07,39.49 68.07,38.79 68,38.73 67.75,38.73 67.24,38.22 66.35,38.22 66.16,38.41 66.16,39.23 66.29,39.36 66.73,39.36 67.11,39.74 67.81,39.74
UG_1.35V on BOTTOM (solid shape): 88.45,14.22 88.45,13.96 88.32,13.83 86.42,13.83 86.35,13.9 86.35,14.02 86.42,14.09 87.31,14.09 87.56,14.34 88.32,14.34
UG_1.35V on BOTTOM (solid shape): 90.61,21.26 90.61,20.06 90.35,19.8 89.91,19.8 89.78,19.93 89.78,21.39 89.91,21.52 90.35,21.52
UG_1.35V on IN3 (solid shape): 89.46,14.09 89.46,13.71 89.34,13.58 87.5,13.58 87.37,13.71 87.37,14.15 87.56,14.34 89.21,14.34
UG_1.35V on IN3 (solid shape): 90.54,21.33 90.54,19.04 90.48,18.98 89.91,18.98 89.78,19.1 89.78,21.33 89.97,21.52 90.35,21.52
UGATE_CHG on BOTTOM (solid shape): 43.97,30.6 43.97,29.9 43.78,29.71 42.98,29.71 42.79,29.9 42.79,30.66 42.92,30.79 43.78,30.79
UGATE_CHG on BOTTOM (solid shape): 48.13,17.07 48.13,16.88 47.24,15.99 47.24,14.98 47.17,14.91 47.05,14.91 46.98,14.98 46.98,16.18 47.17,16.37 47.17,16.63 47.75,17.2 48,17.2
UGATE_CHG on IN3 (solid shape): 48.82,18.03 48.82,17.58 47.49,16.25 47.3,16.25 47.17,16.37 47.17,16.76 47.81,17.39 47.81,18.28 48.57,18.28
UGATE_CHG on IN3 (solid shape): 45.14,30.53 45.14,29.84 44.82,29.52 44.7,29.52 44.49,29.73 42.9,29.73 42.75,29.87 42.75,30.71 42.88,30.84 44.84,30.84
VID_PLLVDD on TOP (solid shape): 71.64,76.02 71.64,71.58 71.64,69.67 71.62,69.65 70.95,69.65 70.9,69.7 70.16,69.7 70.05,69.81 70.05,71.14 70.37,71.46 70.37,76.03 70.56,76.23 71.43,76.23
VID_PLLVDD on BOTTOM (solid shape): 71.9,76.39 71.9,76.23 71.77,75.96 71.91,75.7 71.91,75.47 71.38,74.94 71.14,74.94 71.02,75.06 71.02,75.26 71.09,75.32 71.11,75.35 71.19,75.42 71.19,75.69 71.03,75.84 71.03,76.07 71.1,76.13 71.15,76.21 71.15,76.22 71.47,76.53 71.75,76.53
VL on BOTTOM (solid shape): 65.14,28.95 64.45,28.25 64,28.25 63.87,28.12 63.75,28.12 63.68,28.19 63.68,28.95 63.81,29.07 64.26,29.07 64.57,29.39 64.57,29.77 64.51,29.84 64.51,30.73 65.14,30.73
VREF_VGA on BOTTOM (solid shape): 79.81,43.87 79.81,43.3 79.94,43.17 79.94,43.04 79.88,42.98 79.5,42.98 79.24,42.73 79.24,41.96 79.18,41.9 78.54,41.9 77.65,42.79 76.7,42.79 76.64,42.85 76.64,42.98 76.7,43.04 78.23,43.04 79.18,44 79.69,44
N17415515 on TOP (solid shape): 25.52,113.66 27.81,113.66 28.38,113.08 28.38,110.8 28,110.42 27.04,110.42 27.04,110.99 25.58,110.99 25.58,110.42 25.01,110.42 21.77,113.66 20.25,113.66 20,113.91 20,116.39 20.38,116.77 22.41,116.77
N24017484 on TOP (solid shape): 67.37,81.48 67.55,81.48 67.68,81.34 68.12,81.34 69.16,80.31 69.62,80.31 69.65,80.28 69.65,79.73 69.54,79.62 68.57,79.62 68.39,79.44 66.92,79.44 66.87,79.49 66.87,79.76 66.55,80.08 66.55,81.37 66.66,81.48 67.36,81.48
N24017484 on BOTTOM (solid shape): 68.64,80.63 68.64,79.68 68.55,79.59 68.24,79.59 67.91,79.26 66.61,79.26 66.37,79.5 66.37,80.62 66.58,80.83 68.44,80.83
N24019691 on TOP (solid shape): 77.62,79.9 77.62,78.68 77.47,78.52 75.61,78.52 74.54,79.59 70.01,79.59 69.9,79.7 75.14,79.7 75.14,79.65 75.14,79.6 75.16,79.55 75.18,79.5 75.21,79.46 75.25,79.42 75.29,79.39 75.34,79.37 75.39,79.35 75.44,79.34 75.49,79.34 75.54,79.35 75.59,79.37 75.64,79.39 75.68,79.42 75.72,79.46 75.75,79.5 75.77,79.55 75.79,79.6 75.8,79.65 75.8,79.7 75.79,79.75 75.77,79.8 75.75,79.85 75.72,79.89 75.68,79.93 75.64,79.96 75.59,79.98 75.54,80 75.49,80 75.44,80 75.39,80 75.34,79.98 75.29,79.96 75.25,79.93 75.21,79.89 75.18,79.85 75.16,79.8 75.14,79.75 75.14,79.7 69.9,79.7 69.8,79.8 69.8,80.39 69.84,80.44 77.09,80.44
N24606174 on BOTTOM (solid shape): 181.48,50.66 181.41,50.6 179.63,50.6 179.57,50.66 179.57,50.85 179.63,50.92 180.71,50.92 180.78,50.98 180.78,51.55 180.84,51.62 181.48,51.62
N26262691 on TOP (solid shape): 194.68,89.53 194.68,87.11 196.14,85.65 196.46,85.65 196.72,85.4 196.72,84.95 196.4,84.64 196.21,84.64 195.19,83.62 195.19,80.83 195.07,80.7 194.56,80.7 194.49,80.76 194.49,83.81 195.19,84.51 195.19,85.72 193.99,86.92 193.99,89.46 194.11,89.59 194.62,89.59
N28438430 on BOTTOM (solid shape): 182.94,54.03 182.94,52.06 182.87,52 182.24,52 182.17,52.06 182.17,54.03 182.24,54.09 182.87,54.09
N28438489 on TOP (solid shape): 146.3,115.69 146.3,114.16 146.17,114.04 145.28,114.04 145.15,114.16 145.15,115.56 145.34,115.75 146.23,115.75
N28438489 on BOTTOM (solid shape): 146.42,114.29 147.12,114.29 147.19,114.23 147.19,114.1 147.12,114.04 145.28,114.04 145.15,114.16 145.15,114.42 145.28,114.55 146.17,114.55
N28438498 on TOP (solid shape): 149.35,115.56 149.35,114.86 149.28,114.8 146.93,114.8 146.87,114.86 146.87,115.62 146.93,115.69 149.22,115.69
N28483985 on TOP (solid shape): 35.81,111 35.81,108.7 35.49,108.39 35.49,106.48 35.43,106.42 34.22,106.42 34.09,106.54 34.09,109.15 33.71,109.53 32.19,109.53 32.06,109.66 32.06,111.18 32.26,111.38 35.43,111.38
N28484451 on TOP (solid shape): 32,108.45 32,106.35 32.19,106.16 33.71,106.16 33.84,106.04 33.84,105.15 33.52,104.83 31.11,104.83 30.79,105.15 30.79,108.89 30.92,109.02 31.43,109.02
N28656203 on TOP (solid shape): 199.76,76.89 199.76,76 199.64,75.87 198.81,75.87 198.72,75.89 198.62,75.87 196.53,75.87 196.34,76.06 196.34,76.28 196.4,76.34 196.4,76.76 197.35,76.76 197.61,77.02 199.64,77.02
N28712229 on BOTTOM (solid shape): 82.1,102.04 82.1,101.78 82.04,101.72 81.34,101.72 81.08,101.97 80.32,101.97 80.26,102.04 80.26,102.86 80.32,102.92 81.21,102.92
N28712232 on BOTTOM (solid shape): 81.65,101.02 82.04,101.02 82.1,100.96 82.1,100.77 82.04,100.7 80.32,100.7 80.26,100.77 80.26,101.59 80.32,101.65 81.02,101.65
N28712235 on BOTTOM (solid shape): 79.62,102.8 79.62,100.83 79.56,100.77 78.92,100.77 78.92,102.86 79.56,102.86
N28714854 on BOTTOM (solid shape): 102.29,116.13 102.29,115.94 102.16,115.82 101.53,115.82 101.4,115.69 100.39,115.69 100.32,115.75 100.32,116.64 100.39,116.7 101.72,116.7
N28714856 on BOTTOM (solid shape): 101.72,115.12 102.23,115.12 102.29,115.05 102.29,114.93 102.23,114.86 101.4,114.86 101.02,114.48 100.32,114.48 100.26,114.55 100.26,115.37 100.32,115.43 101.4,115.43
N28714858 on BOTTOM (solid shape): 99.62,116.58 99.62,114.55 99.56,114.48 98.93,114.48 98.86,114.55 98.86,116.58 98.93,116.64 99.56,116.64
N28745344 on BOTTOM (solid shape): 27.43,37.58 28.44,37.58 28.76,37.27 28.76,34.09 28.63,33.96 27.62,33.96 26.98,34.6 26.98,35.11 25.58,36.5 24.31,36.5 24.19,36.63 24.19,38.09 24.31,38.22 26.79,38.22
N28745344 on IN2 (solid shape): 27.43,37.58 28.44,37.58 28.76,37.27 28.76,34.09 28.63,33.96 27.62,33.96 26.98,34.6 26.98,35.11 25.58,36.5 24.31,36.5 24.19,36.63 24.19,38.09 24.31,38.22 26.79,38.22
N28745403 on BOTTOM (solid shape): 48.95,19.8 48.95,19.23 48.89,19.17 46.79,19.17 46.73,19.23 46.73,19.8 46.79,19.87 48.89,19.87
N28745412 on BOTTOM (solid shape): 44.38,19.3 44.38,16.76 45.21,15.93 45.21,14.98 45.14,14.91 45.01,14.91 44.95,14.98 44.95,15.87 44.57,16.25 44.13,16.25 43.94,16.44 42.98,16.44 42.79,16.63 42.79,19.55 42.86,19.61 44.06,19.61
N28745458 on BOTTOM (solid shape): 48.95,18.41 48.95,16.82 47.94,15.8 47.94,15.29 47.55,14.91 47.43,14.91 47.36,14.98 47.36,15.93 48.25,16.82 48.25,17.33 48,17.58 48,18.41 48.06,18.47 48.89,18.47
N28745463 on BOTTOM (solid shape): 36.82,38.41 36.82,35.23 35.24,35.23 35.24,34.6 36.82,34.6 36.82,33.77 36.51,33.46 29.71,33.46 29.39,33.77 29.39,38.66 29.71,38.98 36.25,38.98
N28745481 on TOP (solid shape): 52.25,28.88 52.25,27.87 52.13,27.74 48.06,27.74 47.87,27.93 47.87,29.14 48.06,29.33 51.81,29.33
N28745481 on BOTTOM (solid shape): 52.63,34.15 52.63,28.06 52.32,27.74 44.63,27.74 44.57,27.8 44.57,30.34 45.08,30.85 45.52,30.85 46.16,31.49 46.16,34.45 45.98,34.62 45.36,34.62 45.36,35.18 43.4,35.18 43.4,34.64 42.63,34.64 41.84,35.42 41.84,38.6 42.41,39.17 47.62,39.17
N28745526 on BOTTOM (solid shape): 36.19,28.19 36.19,22.22 34.47,20.5 27.49,20.5 27.11,20.88 27.11,21.58 27.17,21.64 28.7,21.64 28.7,22.34 27.17,22.34 27.11,22.41 27.11,25.39 27.55,25.84 31.93,25.84 32.31,26.22 32.31,28.82 35.55,28.82
N28745613 on BOTTOM (solid shape): 42.79,22.66 42.79,21.58 42.6,21.39 42.22,21.39 41.4,20.57 41.01,20.57 40.82,20.76 40.82,23.04 42.41,23.04
N28745648 on BOTTOM (solid shape): 40.63,18.28 41.65,18.28 41.78,18.15 41.78,16.63 41.2,16.06 38.6,16.06 38.54,16.12 38.54,18.47 38.66,18.6 40.32,18.6
N28745686 on TOP (solid shape): 24.6,39.27 24.6,38.12 24.31,37.84 21.84,37.84 21.74,37.93 21.74,39.27 21.87,39.39 24.47,39.39
N32012960 on BOTTOM (solid shape): 148.77,117.02 148.77,116.39 149.41,115.75 149.41,115.12 149.35,115.05 148.71,115.05 148.01,115.75 148.01,117.02 148.2,117.21 148.58,117.21
N32012964 on BOTTOM (solid shape): 147.19,113.78 147.19,113.47 147,113.28 145.28,113.28 145.15,113.4 145.15,113.72 145.28,113.85 147.12,113.85
N32012964 on IN1 (solid shape): 148.14,119.82 148.14,118.67 147.82,118.36 147.57,118.36 147.06,118.86 147.06,119.82 147.19,119.94 148.01,119.94
N32012964 on IN1 (solid shape): 147.31,114.16 147.31,113.72 146.87,113.28 145.28,113.28 145.15,113.4 145.15,113.72 145.28,113.85 146.36,113.85 146.55,114.04 146.55,114.23 147.25,114.23
N33124395 on BOTTOM (solid shape): 85.46,16.56 85.02,16.12 85.02,14.72 84.96,14.66 84.83,14.66 84.77,14.72 84.77,15.61 84.58,15.8 84,15.8 83.31,16.5 83.31,17.2 85.46,17.2
N33124472 on TOP (solid shape): 94.42,17.45 94.42,15.1 94.35,15.04 93.47,15.04 93.4,15.1 93.4,15.74 93.15,15.99 92.39,15.99 92.39,17.39 92.51,17.52 94.35,17.52
N33966313 on BOTTOM (solid shape): 62.6,53.08 62.6,52.7 62.22,52.32 61.46,52.32 61.33,52.44 61.33,53.33 61.46,53.46 62.22,53.46
N33966313 on BOTTOM (solid shape): 75.24,45.46 75.24,44.06 75.18,44 75.05,44 74.99,44.06 74.99,44.95 74.29,45.65 74.29,45.9 74.42,46.03 74.67,46.03
N33966313 on IN3 (solid shape): 63.05,53.01 63.05,52.51 62.86,52.32 61.52,52.32 61.33,52.51 61.33,53.33 61.46,53.46 62.6,53.46
N33966313 on IN3 (solid shape): 75.3,45.71 75.3,45.27 75.05,45.01 74.61,45.01 73.34,46.28 73.34,46.47 73.78,46.92 74.1,46.92
N39352229 on BOTTOM (solid shape): 64.38,9.64 64.38,9.14 64.32,9.07 62.22,9.07 62.16,9.14 62.16,9.64 62.22,9.71 64.32,9.71
N39352417 on BOTTOM (solid shape): 66.54,27.99 66.54,27.04 66.48,26.98 65.4,26.98 65.08,27.3 64.06,27.3 64,27.36 64,27.99 64.06,28.06 66.48,28.06
N39352440 on BOTTOM (solid shape): 63.24,21.52 65.27,21.52 65.33,21.45 65.33,20.95 65.27,20.88 62.86,20.88 62.16,21.58 62.16,21.9 62.22,21.96 62.79,21.96

Small or netless copper shapes (teardrops, artwork), in the pictures only: 177 on TOP, 217 on BOTTOM, 4 on IN1, 31 on IN2, 35 on IN3

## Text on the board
Ref Des/Silkscreen Bottom: FAN | RTC | H18 | H17 | DIMMA | DIMMB | DDR3L | Support | SODIMM-only | H19 | HDD | SPK | EDP | IO | SODIMM-Only support DDR3L | WLAN
User.Comments: BAV00 | LA-D051P | Rita_Weng | 2015-07-15 | 2016-07-15 | 1.0(A00) | PARTITION_2 | PARTITION_3 | PARTITION_4
Ref Des/Silkscreen Top: TP | LED | KB | KBBL
BODY_CENTER: GND | +5VALW | +1.35V_MEM_GFX | +3VS | +3VALW | GNDA | +VGA_CORE | +CPU_CORE | +1.05VS_PCH | +LAN_VDD33
User.11: TP | 191.65 | 182.90 | 163.52 | 149.55 | 135.55 | 5.11 | 2.30 | 0.85 | 0.00 | 10.00 | 16.82 | 4.00 | 29.10 | 57.05 | 75.25 | 81.90 | 94.25 | 102.00 | 6.50 | 19.95 | 35.03 | 49.33 | 58.55 | 60.50 | 185.75 | 112.65 | 84.10 | 2.65
User.12: TP | V-CUT | 110.50 | 46.75 | 49.33 | 107.45 | 19.80 | 19.95 | 35.03 | 44.10 | 71.10 | 74.85 | 84.06 | 202.65 | 163.52 | 149.55 | 139.40 | 135.55 | 108.25 | 95.85 | 0.00 | 10.00 | 197.35 | 178.75 | 177.00 | 110.30 | 31.93 | 23.94 | 4.20 | 4.00 | 60.98 | 104.75 | 105.80
User.13: TP | V-CUT | 163.52 | 149.55 | 135.55 | 0.00 | 10.00 | 4.00 | 118.80 | 19.95 | 49.33 | 35.03
User.14: TP | V-CUT | 44.10 | 35.03 | 49.33 | 19.95 | 163.52 | 149.55 | 139.40 | 135.55 | 0.00
User.15: 182.30 | 176.60 | 170.60 | 0.50 | 0.05 | 120.95 | 102.60 | 39.40 | 22.67 | 8.90 | 6.00 | 0.00 | 108.80 | 13.40 | 22.40 | 27.45 | 37.70 | 49.00 | 114.80 | 96.50 | 86.70 | 25.45 | 26.70 | 61.00 | 109.00 | 115.30 | 182.60 | 121.60 | 103.40 | 38.60 | 21.40 | 9.40 | 4.90
User.16: {\Fgdt;n}\Ftxt;8.00 | {\Fgdt;n}\Ftxt;2.80 | 2.80 | {\Fgdt;n}\Ftxt;3.30 | {\Fgdt;n}\Ftxt;6.00 | {\Fgdt;n}\Ftxt;3.60 | {\Fgdt;n}\Ftxt;7.00 | {\Fgdt;n}\Ftxt;9.00 | 3.30 | 5.50 | {\Fgdt;n}\Ftxt;8.55 | 4.80
User.39: L1-TOP | L2-GND1 | L3-IN1 | L4-VCC | L5-IN2 | L6-IN3 | L7-GND2 | L8-BOT | LAYER | NAME
User.42: FIGURE | SIZE | 8.0 | 10.0 | 22.0 | 28.0 | 37.0 | 47.0 | 110.0 | 130.0 | 142.0 | 43.0 | 63.0 | 71.0 | 59.0x24.0 | 63.0x35.0 | 71.0x31.0 | 87.0x24.0 | 102.0x31.0 | 110.0x39.0 | 130.0x110.0 | 189.0x110.0 | DRILL CHART: TOP to BOTTOM | ALL UNITS ARE IN MILS | TOLERANCE | +3.0/-3.0 | +2.0/-2.0 | PLATED | NON-PLATED | QTY | 5133 | 226 | 19 | 18 | 8 | 9 | 10 | 3 | 4 | 5 | 2 | 7 | 1
